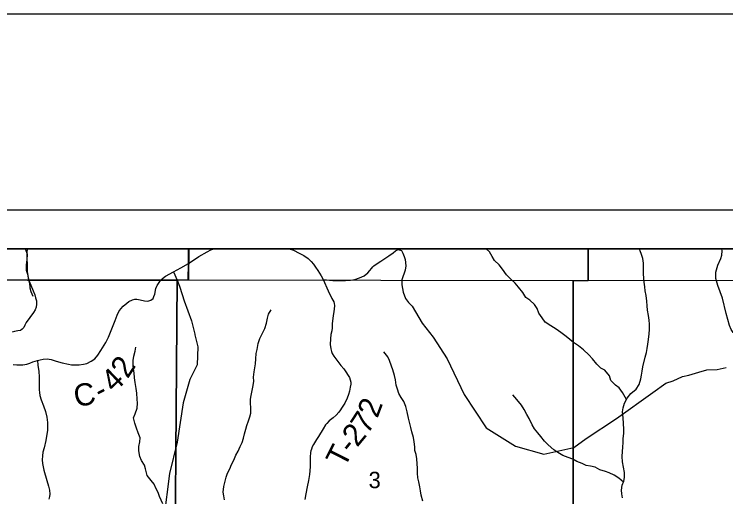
# Model space of a CAD drawing. Extents: x 0 to 34, y -8.9 to 22.
# Drawn here: x 24.719 to 26.538, y 20.766 to 22 of the extents above; entities that cross this region are included whole.
import ezdxf

# ---------------------------------------------------------------- set-up
doc = ezdxf.new("R2010")
doc.units = 0
for name, color, linetype in [('GM_X_Corporation', 7, 'Continuous'), ('GM_X_County_Road', 7, 'Continuous'), ('GM_X_County_Road_Text', 7, 'Continuous'), ('GM_X_Minor_River', 7, 'Continuous'), ('GM_X_Section_Text', 7, 'Continuous'), ('GM_X_Township_Road', 7, 'Continuous'), ('GM_X_Township_Road_Text', 7, 'Continuous'), ('SH_Border', 7, 'Continuous'), ('SH_Cut_Line', 7, 'Continuous'), ('SH_Data', 7, 'Continuous')]:
    doc.layers.add(name, color=color, linetype=linetype)

msp = doc.modelspace()

# ---------------------------------------------------------------- linework, layer by layer
at = {"layer": 'GM_X_Corporation'}
for points in [[(30.5167, 21.4), (23.7167, 21.4), (23.7167, 19.34), (24.5181, 19.3295), (25.0504, 19.3237), (25.1066, 19.3232), (25.1068, 18.8675), (25.1136, 18.8385), (25.1229, 18.6966), (25.125, 18.6354), (25.1216, 18.6194), (25.1124, 18.5932), (25.1045, 18.3117), (25.2083, 18.3108), (25.7381, 18.312), (26.1399, 18.3037), (26.1391, 17.8847), (26.1361, 17.3278)], [(28.2203, 21.4), (25.1649, 21.4), (25.1646, 21.3656), (25.1645, 21.3632), (25.1639, 21.3208), (25.1355, 21.32), (25.0937, 21.3201), (25.0907, 21.3201), (24.7567, 21.3198), (24.7536, 21.3198), (23.7167, 21.3241), (23.7167, 19.34)]]:
    msp.add_lwpolyline(points, dxfattribs=at)
for points in [[(25.1649, 21.4), (23.7167, 21.4), (23.7167, 21.3241), (24.7536, 21.3198), (24.7567, 21.3198), (25.0907, 21.3201), (25.0937, 21.3201), (25.1355, 21.32), (25.1639, 21.3208), (25.1645, 21.3632), (25.1646, 21.3656)], [(25.1653, 21.4), (24.1596, 21.4), (24.1588, 21.3221), (25.1357, 21.3204), (25.1645, 21.3207)], [(26.1865, 21.4), (25.1653, 21.4), (25.1645, 21.3207), (26.1479, 21.3194), (26.1865, 21.3191)], [(27.2077, 21.4), (26.1865, 21.4), (26.1865, 21.3191), (27.2076, 21.3201)], [(24.1402, 21.3227), (24.1588, 21.3221), (25.1357, 21.3204), (25.1285, 20.3218), (24.1258, 20.3236)], [(25.1357, 21.3204), (25.1645, 21.3207), (26.1479, 21.3194), (26.1486, 20.3228), (25.1285, 20.3218)], [(26.1479, 21.3194), (26.1865, 21.3191), (27.2076, 21.3201), (27.2068, 20.322), (26.1486, 20.3228)]]:
    msp.add_lwpolyline(points, close=True, dxfattribs=at)
at = {"layer": 'GM_X_County_Road'}
for points in [[(24.7526, 21.4), (24.7516, 21.3898), (24.7518, 21.3723), (24.7521, 21.3617), (24.7521, 21.3607)], [(25.0839, 21.3044), (25.0847, 21.3061), (25.0911, 21.3164), (25.0939, 21.3195), (25.0982, 21.3244), (25.1059, 21.3305), (25.1265, 21.3413), (25.1454, 21.3516), (25.1648, 21.3627), (25.1916, 21.3805), (25.2123, 21.3922), (25.2223, 21.3972), (25.2293, 21.4)], [(24.7521, 21.3607), (24.7526, 21.3423), (24.7541, 21.331), (24.7569, 21.3193), (24.7613, 21.3068), (24.7675, 21.2927), (24.7716, 21.2821), (24.774, 21.2743), (24.7759, 21.2667), (24.7762, 21.2584), (24.775, 21.2506), (24.7728, 21.2439), (24.7682, 21.2373), (24.7499, 21.2118), (24.7464, 21.2044), (24.7441, 21.1992), (24.7399, 21.1942), (24.7349, 21.1909), (24.7282, 21.1899), (24.7198, 21.1886), (24.7137, 21.1865)], [(24.987, 21.2401), (24.9915, 21.2462), (24.9979, 21.2532), (25.0071, 21.2612), (25.0125, 21.265), (25.0214, 21.2694), (25.0275, 21.2709), (25.0329, 21.2714), (25.0415, 21.2697), (25.0526, 21.2671), (25.061, 21.2664), (25.0688, 21.2685), (25.0747, 21.273), (25.0765, 21.2779), (25.0784, 21.284), (25.0814, 21.2984), (25.0839, 21.3044)], [(24.7169, 21.1042), (24.726, 21.1032), (24.7413, 21.1037), (24.7512, 21.1054), (24.7594, 21.1077), (24.7668, 21.1108), (24.7789, 21.1141), (24.7854, 21.1161), (24.7932, 21.1181), (24.8037, 21.1185), (24.814, 21.1169), (24.8265, 21.1131), (24.8418, 21.1084), (24.8577, 21.1047), (24.8655, 21.1035), (24.8744, 21.1032), (24.8852, 21.1035), (24.8962, 21.1047), (24.9052, 21.107), (24.9157, 21.1124), (24.925, 21.1183), (24.9328, 21.1281), (24.9409, 21.1404), (24.9535, 21.1607), (24.9599, 21.1737), (24.9674, 21.1911), (24.9772, 21.2169), (24.9822, 21.2307), (24.9864, 21.2394), (24.987, 21.2401)]]:
    msp.add_lwpolyline(points, dxfattribs=at)
at = {"layer": 'GM_X_Minor_River'}
for points in [[(24.7473, 21.4), (24.7479, 21.3984), (24.7521, 21.3863), (24.7515, 21.3722), (24.7497, 21.3589), (24.7501, 21.3453), (24.7528, 21.3355), (24.7552, 21.3252), (24.7579, 21.3123), (24.7595, 21.3006), (24.7619, 21.2908), (24.7669, 21.2786)], [(26.2843, 21.0146), (26.2744, 21.0328), (26.266, 21.0441), (26.2564, 21.0513), (26.2446, 21.0629), (26.2415, 21.0754), (26.2292, 21.0894), (26.2193, 21.095), (26.2086, 21.1052), (26.1975, 21.1184), (26.1883, 21.1293), (26.1746, 21.1414), (26.1616, 21.1519), (26.1494, 21.1606), (26.1398, 21.1681), (26.1299, 21.176), (26.1166, 21.1858), (26.1044, 21.1948), (26.0914, 21.2027), (26.0769, 21.2124), (26.0689, 21.2234), (26.0608, 21.2351), (26.0558, 21.2476), (26.0493, 21.2574), (26.0374, 21.2687), (26.0275, 21.2754), (26.0191, 21.2879), (26.0083, 21.3019), (25.9995, 21.3121), (25.9881, 21.3234), (25.9774, 21.3335), (25.9674, 21.3479), (25.9586, 21.3588), (25.9468, 21.3705), (25.9414, 21.3803), (25.9341, 21.3924), (25.9256, 21.4)], [(26.3264, 21.3752), (26.3233, 21.3851), (26.3191, 21.3949), (26.3168, 21.4)], [(26.2746, 20.7631), (26.2727, 20.773), (26.2719, 20.7828), (26.2737, 20.7957), (26.2778, 20.806), (26.2796, 20.8155), (26.2795, 20.8276), (26.2768, 20.8416), (26.2744, 20.8553), (26.2732, 20.8685), (26.2746, 20.8818), (26.2753, 20.8925), (26.276, 20.9046), (26.2763, 20.9152), (26.2774, 20.9277), (26.2777, 20.9391), (26.2768, 20.9535), (26.2756, 20.9676), (26.2747, 20.9835), (26.2762, 20.993), (26.2795, 21.0055), (26.2859, 21.0177), (26.2953, 21.0303), (26.3093, 21.0414), (26.3168, 21.0532), (26.3209, 21.0676), (26.3227, 21.0771), (26.3245, 21.087), (26.3264, 21.0984), (26.3323, 21.1227), (26.3356, 21.1348), (26.3374, 21.1455), (26.3393, 21.1565), (26.3411, 21.1682), (26.3429, 21.1823), (26.3436, 21.1941), (26.3435, 21.2073), (26.3427, 21.2172), (26.3407, 21.2293), (26.3383, 21.2433), (26.3375, 21.2543), (26.3363, 21.2661), (26.3346, 21.2805), (26.3323, 21.293), (26.3311, 21.3025), (26.3295, 21.3146), (26.3287, 21.3241), (26.3278, 21.3373), (26.3277, 21.3502), (26.328, 21.3631), (26.3264, 21.3752)], [(25.2567, 20.758), (25.2555, 20.7682), (25.2535, 20.7777), (25.255, 20.7925), (25.2583, 20.8058), (25.2609, 20.8164), (25.2642, 20.8263), (25.2702, 20.8374), (25.2751, 20.8488), (25.2807, 20.8598), (25.2856, 20.8724), (25.2916, 20.8826), (25.2968, 20.8941), (25.3017, 20.9047), (25.305, 20.9161), (25.308, 20.9267), (25.311, 20.9385), (25.3136, 20.9484), (25.318, 20.9602), (25.3218, 20.9701), (25.324, 20.98), (25.3239, 20.9932), (25.323, 21.0054), (25.3234, 21.0152), (25.3252, 21.0251), (25.3278, 21.038), (25.33, 21.0505), (25.3314, 21.0612), (25.3313, 21.0722), (25.3324, 21.0851), (25.3342, 21.0957), (25.3364, 21.1063), (25.3367, 21.1189), (25.3382, 21.1325), (25.34, 21.1428), (25.3433, 21.1576), (25.3474, 21.1705), (25.3519, 21.1812), (25.3601, 21.196), (25.3646, 21.2097), (25.3664, 21.223), (25.3694, 21.2329), (25.3758, 21.2439)], [(25.0996, 20.7479), (25.0907, 20.7664), (25.0876, 20.777), (25.0815, 20.788), (25.0772, 20.7978), (25.0692, 20.8076), (25.0592, 20.8204), (25.0546, 20.8371), (25.0519, 20.8469), (25.0446, 20.8587), (25.0407, 20.8689), (25.0379, 20.8833), (25.0379, 20.8943), (25.0401, 20.9068), (25.0411, 20.9163), (25.0365, 20.9295), (25.0315, 20.9416), (25.0276, 20.9541), (25.0245, 20.9681), (25.0286, 20.9784), (25.0334, 20.9921), (25.0341, 21.0054), (25.0333, 21.0156), (25.0328, 21.0308), (25.0312, 21.0425), (25.0284, 21.0581), (25.0268, 21.0702), (25.026, 21.0831), (25.0244, 21.0926), (25.0232, 21.1035), (25.0231, 21.1145), (25.025, 21.1259), (25.0283, 21.1385), (25.0301, 21.1487)], [(25.7636, 20.7545), (25.7597, 20.7704), (25.7578, 20.7814), (25.7566, 20.7912), (25.7534, 20.8041), (25.7507, 20.8147), (25.7503, 20.8261), (25.7502, 20.8394), (25.7497, 20.85), (25.7489, 20.8632), (25.7465, 20.8738), (25.7438, 20.8841), (25.7434, 20.8935), (25.7421, 20.9068), (25.7398, 20.9174), (25.7355, 20.9322), (25.7328, 20.9432), (25.7304, 20.953), (25.7269, 20.967), (25.7234, 20.9829), (25.7207, 20.9966), (25.7149, 21.0094), (25.7083, 21.0196), (25.7026, 21.0302), (25.6987, 21.0408), (25.696, 21.051), (25.694, 21.065), (25.6916, 21.0764), (25.6874, 21.0904), (25.6835, 21.1002), (25.6785, 21.1142), (25.6742, 21.1241), (25.6643, 21.1362)], [(26.2766, 20.8031), (26.2652, 20.8131), (26.253, 20.821), (26.2401, 20.827), (26.2305, 20.8303), (26.2161, 20.8348), (26.2043, 20.8415), (26.1925, 20.8441), (26.1815, 20.8463), (26.1712, 20.8512), (26.1578, 20.8557), (26.1472, 20.8617), (26.1354, 20.8665), (26.1221, 20.8714), (26.1091, 20.8792), (26.0984, 20.8856), (26.0843, 20.8988), (26.0747, 20.9082), (26.0652, 20.9199), (26.0575, 20.9297), (26.0495, 20.9395), (26.0433, 20.9501), (26.0356, 20.9664), (26.0299, 20.9766), (26.0233, 20.9887), (26.0157, 21), (26.0045, 21.0143), (25.9942, 21.0268)]]:
    msp.add_lwpolyline(points, dxfattribs=at)
at = {"layer": 'GM_X_Township_Road'}
for points in [[(25.4224, 21.4), (25.4331, 21.3963), (25.4481, 21.3892), (25.4596, 21.3828), (25.4703, 21.3754), (25.4783, 21.3673), (25.4843, 21.3605), (25.4898, 21.3531), (25.4954, 21.3449), (25.5042, 21.3311), (25.5091, 21.3218)], [(25.5091, 21.3218), (25.5334, 21.3188), (25.5488, 21.3186), (25.5664, 21.3194), (25.579, 21.3202), (25.5896, 21.3217), (25.6023, 21.3256), (25.614, 21.3311), (25.6229, 21.339), (25.6284, 21.3443), (25.6328, 21.3498), (25.6362, 21.354), (25.6388, 21.3566), (25.6444, 21.3611), (25.6562, 21.3686), (25.6771, 21.3819), (25.6882, 21.3899), (25.6939, 21.3947), (25.701, 21.3979), (25.7093, 21.3959), (25.7131, 21.3888), (25.7158, 21.3808), (25.7188, 21.3728), (25.7205, 21.3568), (25.7185, 21.3452), (25.7102, 21.3203), (25.7105, 21.3082), (25.7137, 21.2895), (25.7197, 21.2732), (25.7274, 21.2625), (25.7368, 21.253), (25.7618, 21.2101), (25.7905, 21.1739), (25.8258, 21.1184), (25.8697, 21.0272), (25.9254, 20.9426), (26.0005, 20.895), (26.073, 20.8751), (26.1495, 20.892), (26.1812, 20.9146), (26.2591, 20.9659), (26.3515, 21.0323), (26.3852, 21.0562), (26.4037, 21.0628), (26.4274, 21.0735), (26.4443, 21.0768), (26.4694, 21.0846), (26.4898, 21.0903), (26.5162, 21.0917), (26.5392, 21.0962)], [(26.6618, 21.1091), (26.6502, 21.1183), (26.6108, 21.1465), (26.5741, 21.1719), (26.5636, 21.18), (26.5574, 21.1862), (26.552, 21.194), (26.548, 21.204), (26.5394, 21.2348), (26.5296, 21.2742), (26.518, 21.3064), (26.5129, 21.3238), (26.5132, 21.3405), (26.5184, 21.358), (26.5258, 21.3752), (26.5284, 21.3835), (26.5291, 21.3953), (26.528, 21.4)], [(25.1265, 21.3413), (25.1358, 21.3195), (25.1415, 21.3047)], [(25.5091, 21.3218), (25.5218, 21.2924), (25.5315, 21.2734), (25.5361, 21.2647), (25.5374, 21.2603), (25.538, 21.2549), (25.5376, 21.2454), (25.5335, 21.2226), (25.5321, 21.208), (25.5317, 21.1977), (25.531, 21.1906), (25.5289, 21.181), (25.5275, 21.1697), (25.527, 21.1556), (25.5283, 21.1442), (25.5301, 21.1375), (25.5325, 21.1322), (25.5364, 21.1254), (25.5544, 21.1018), (25.5617, 21.0933), (25.5672, 21.0856), (25.5729, 21.0763), (25.576, 21.0708), (25.5783, 21.0651), (25.5794, 21.0594), (25.5797, 21.0542), (25.5785, 21.0466), (25.5761, 21.0362), (25.5739, 21.0271), (25.5708, 21.0178), (25.5641, 21.0052), (25.5595, 20.9976), (25.5562, 20.9924), (25.5531, 20.988), (25.5489, 20.9826), (25.5419, 20.9749), (25.5348, 20.9682), (25.5247, 20.9598), (25.5185, 20.9535), (25.5153, 20.9497), (25.5088, 20.9397), (25.497, 20.9197), (25.4924, 20.9127), (25.4847, 20.8999), (25.4813, 20.8933), (25.4791, 20.8879), (25.4777, 20.8838), (25.4768, 20.8789), (25.4758, 20.867), (25.4759, 20.8529), (25.4755, 20.8423), (25.4742, 20.8232), (25.4718, 20.8075), (25.4684, 20.7909), (25.4651, 20.7735), (25.4623, 20.7589)], [(25.1415, 21.3047), (25.1426, 21.3019), (25.1538, 21.2669), (25.1728, 21.2158), (25.1807, 21.182)], [(25.1807, 21.182), (25.1812, 21.18), (25.1885, 21.1491), (25.1869, 21.1035), (25.1686, 21.0654), (25.1509, 21.0064), (25.1361, 20.9053), (25.1162, 20.8255), (25.1019, 20.7115), (25.1048, 20.5881), (25.1188, 20.4352), (25.124, 20.3529), (25.1288, 20.2201), (25.1313, 20.146)], [(24.7789, 21.1141), (24.78, 21.1028), (24.7823, 21.0859), (24.7826, 21.0727), (24.7831, 21.0493), (24.7829, 21.0394), (24.7835, 21.0328), (24.7846, 21.0245), (24.788, 21.0135), (24.7943, 20.9989), (24.7996, 20.984), (24.8026, 20.9693), (24.804, 20.9559), (24.804, 20.9365), (24.8, 20.9099), (24.7954, 20.8914), (24.7926, 20.8796), (24.7916, 20.8705), (24.7908, 20.8605), (24.7914, 20.8509), (24.7953, 20.8337), (24.803, 20.8077), (24.807, 20.7927), (24.8093, 20.7832), (24.8099, 20.7727), (24.8093, 20.7664), (24.8077, 20.7596)]]:
    msp.add_lwpolyline(points, dxfattribs=at)
at = {"layer": 'SH_Border'}
msp.add_lwpolyline([(1.5, 21.5), (33.5, 21.5), (33.5, 0.5), (1.5, 0.5)], close=True, dxfattribs=at)
at = {"layer": 'SH_Cut_Line'}
msp.add_lwpolyline([(0, 0), (34, 0), (34, 22), (0, 22)], close=True, dxfattribs=at)
at = {"layer": 'SH_Data'}
for points in [[(23.6167, 21.5), (30.6167, 21.5), (30.6167, 14.5), (23.6167, 14.5)], [(23.7167, 21.4), (30.5167, 21.4), (30.5167, 14.6), (23.7167, 14.6)]]:
    msp.add_lwpolyline(points, close=True, dxfattribs=at)

# ---------------------------------------------------------------- texts
at = {"layer": 'GM_X_County_Road_Text'}
for s, rotation, p in [('2', 57.448, (25.0093, 21.0661)), ('4', 43.5784, (24.9744, 21.0304)), ('C', 11.1982, (24.8773, 20.9944)), ('-', 28.0411, (24.9402, 21.0096))]:
    msp.add_text(s, height=0.0568, rotation=rotation, dxfattribs=at).set_placement(p)
at = {"layer": 'GM_X_Section_Text'}
msp.add_text('3', height=0.0419, rotation=0, dxfattribs=at).set_placement((25.6252, 20.7879))
at = {"layer": 'GM_X_Township_Road_Text'}
for s, rotation, p in [('2', 69.4488, (25.6478, 20.965)), ('7', 56.721, (25.6224, 20.9235)), ('2', 50.3876, (25.596, 20.891)), ('T', 63.0689, (25.5639, 20.8377)), ('-', 51.05, (25.5814, 20.873))]:
    msp.add_text(s, height=0.0568, rotation=rotation, dxfattribs=at).set_placement(p)

doc.saveas('drawing.dxf')
